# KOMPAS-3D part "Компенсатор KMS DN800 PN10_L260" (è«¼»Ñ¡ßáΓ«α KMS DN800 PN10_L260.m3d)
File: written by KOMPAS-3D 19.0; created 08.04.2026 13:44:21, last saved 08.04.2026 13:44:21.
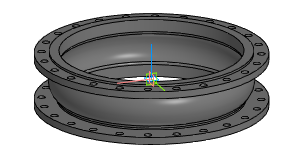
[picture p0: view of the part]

Document properties: Автор: Энергия; Полное имя файла: Z:\3.Личные\kachalov\3d для проектировщиков\7.1 Компенсатор\stp_Компенсатор KSM\Компенсатор KMS DN800 PN10_L260.m3d

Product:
- Part/product: Компенсатор KMS DN800 PN10_L260

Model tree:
1. Операция без истории:1  (labels: Компенсатор KMS DN800 PN10_L260)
